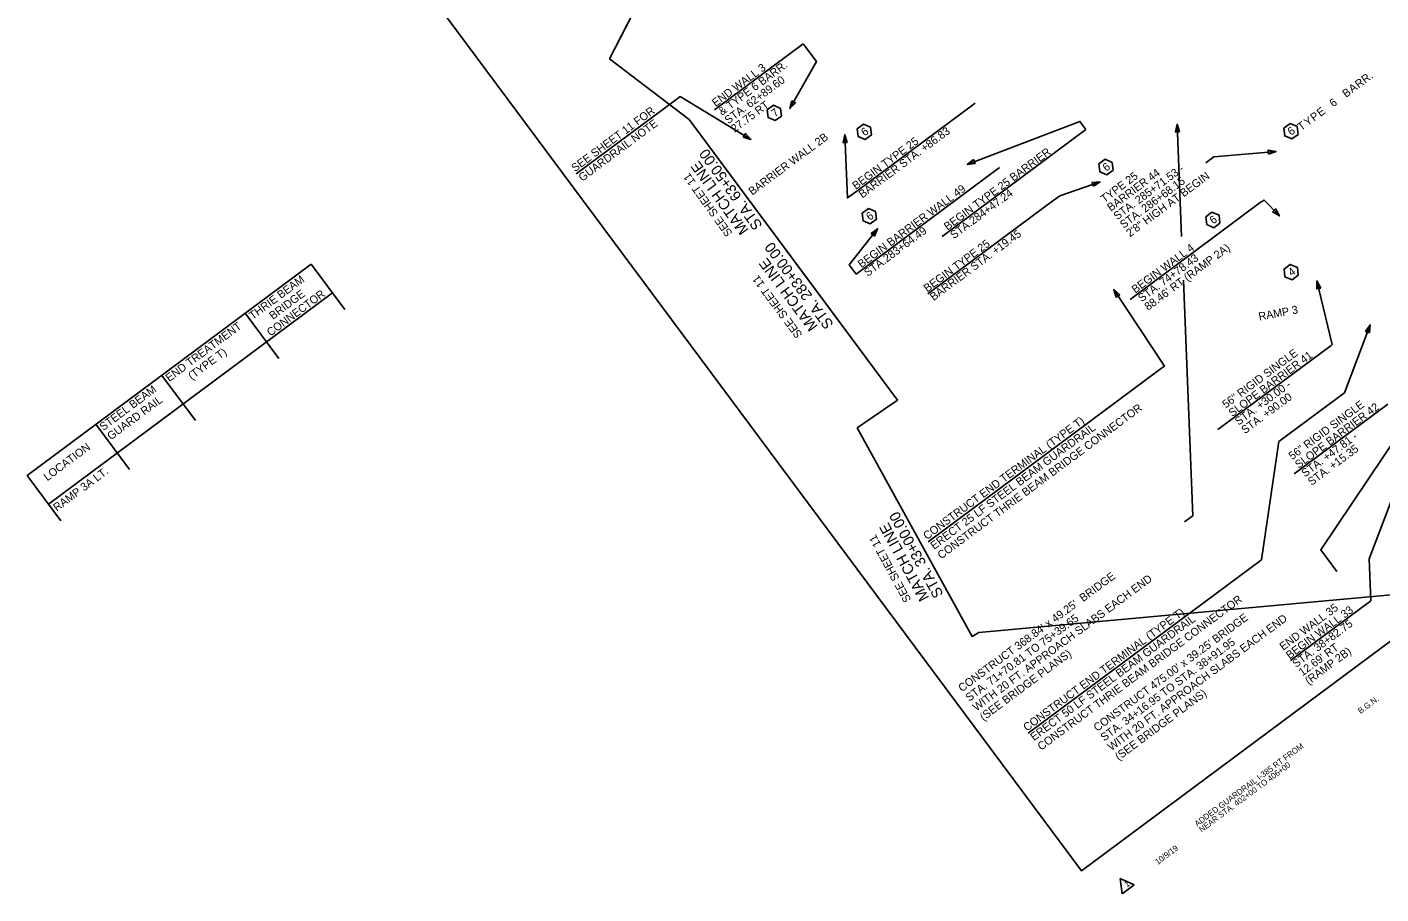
# Model space of a CAD drawing. Extents: x 1609621 to 1611756, y 1093008 to 1094970.
# Drawn here: x 1609621 to 1610636, y 1093008 to 1093658 of the extents above; entities that cross this region are included whole.
import ezdxf

# ---------------------------------------------------------------- set-up
doc = ezdxf.new("R2010")
doc.units = 0
for name, color, linetype in [('Level 2', 7, 'Continuous'), ('Plan_Clip', 7, 'Continuous'), ('RD_PD_GR_TX', 7, 'Continuous'), ('RD_SHT_MatchLine', 7, 'Continuous'), ('RD_SHT_TX', 7, 'Continuous'), ('RD_TX_Bridge', 7, 'Continuous'), ('RD_TX_RoadID', 7, 'Continuous')]:
    doc.layers.add(name, color=color, linetype=linetype)

msp = doc.modelspace()

# ---------------------------------------------------------------- linework, layer by layer
at = {"layer": 'Level 2'}
msp.add_lwpolyline([(1609840.9, 1093793), (1611185.2, 1094792.2), (1611755.8, 1094024.6), (1610411.6, 1093025.3)], close=True, dxfattribs=at)
at = {"layer": 'Plan_Clip'}
msp.add_lwpolyline([(1610675.5, 1094282.2), (1610541, 1094302.1), (1610507.1, 1094195.8), (1610487.7, 1094201.2), (1610383.3, 1094027.8), (1610263.9, 1094064.6), (1610138, 1093954.5), (1610138.1, 1093790.9), (1610057.7, 1093634.1), (1610117.5, 1093588.6), (1610273.7, 1093378.3), (1610243.5, 1093357.4), (1610329.6, 1093201), (1610334.7, 1093203.9), (1610646.7, 1093232.4)], dxfattribs=at)
msp.add_lwpolyline([(1610675.5, 1094282.2), (1610541, 1094302.1), (1610507.1, 1094195.8), (1610487.7, 1094201.2), (1610383.3, 1094027.8), (1610263.9, 1094064.6), (1610138, 1093954.5), (1610138.1, 1093790.9), (1610057.7, 1093634.1), (1610117.5, 1093588.6), (1610273.7, 1093378.3), (1610243.5, 1093357.4), (1610329.6, 1093201), (1610334.7, 1093203.9), (1610646.7, 1093232.4)], dxfattribs=at)
at = {"layer": 'RD_PD_GR_TX'}
for p, q in [((1610107.4, 1093603.5), (1610032.7, 1093547.9)), ((1609620.9, 1093321.8), (1609833.9, 1093480.1)), ((1609833.9, 1093480.1), (1609859.1, 1093446.2)), ((1609636.8, 1093300.3), (1609849.8, 1093458.7)), ((1609784.5, 1093443.4), (1609809.7, 1093409.5)), ((1609721.8, 1093396.8), (1609747.1, 1093362.9)), ((1610471.6, 1093402.1), (1610296.6, 1093272)), ((1609672.4, 1093360.1), (1609697.6, 1093326.2)), ((1609620.9, 1093321.8), (1609646.1, 1093287.8)), ((1610546.6, 1093258.5), (1610371.5, 1093128.4))]:
    msp.add_line(p, q, dxfattribs=at)
for points in [[(1610107.4, 1093603.5), (1610110.7, 1093605.9), (1610163.7, 1093573.7)], [(1610471.6, 1093402.1), (1610473.8, 1093403.7), (1610435.8, 1093461.1)], [(1610546.6, 1093258.5), (1610559.6, 1093347.1), (1610608.9, 1093383.7), (1610628.2, 1093434.6)]]:
    msp.add_lwpolyline(points, dxfattribs=at)
for points in [[(1610158, 1093575.4), (1610163.7, 1093573.7), (1610159.6, 1093578.1)], [(1610440.3, 1093457.2), (1610435.8, 1093461.1), (1610437.7, 1093455.4)], [(1610627.6, 1093428.6), (1610628.2, 1093434.6), (1610624.7, 1093429.7)]]:
    msp.add_lwpolyline(points, close=True, dxfattribs=at)
at = {"layer": 'RD_SHT_MatchLine'}
for p, q in [((1610138.1, 1093790.9), (1610057.7, 1093634.1)), ((1610243.5, 1093357.4), (1610329.6, 1093201))]:
    msp.add_line(p, q, dxfattribs=at)
msp.add_lwpolyline([(1610273.7, 1093378.3), (1610206.9, 1093468.2), (1610117.5, 1093588.6)], dxfattribs=at)
at = {"layer": 'RD_SHT_TX'}
for p, q in [((1610202.9, 1093645.5), (1610136.4, 1093596)), ((1610331.9, 1093601), (1610243.1, 1093535)), ((1610414.9, 1093581.1), (1610307.2, 1093501)), ((1610350.1, 1093552.7), (1610242.6, 1093472.8)), ((1610385.4, 1093524.1), (1610296.5, 1093458)), ((1610545.6, 1093526.3), (1610448, 1093453.8)), ((1610598.9, 1093419.3), (1610513.9, 1093356.2)), ((1610641.3, 1093375.1), (1610571.1, 1093322.9)), ((1610628.5, 1093227.7), (1610568.3, 1093182.9)), ((1610440.6, 1093019.4), (1610451.2, 1093014.7)), ((1610440.6, 1093019.4), (1610442.1, 1093007.9)), ((1610442.1, 1093007.9), (1610451.2, 1093014.7))]:
    msp.add_line(p, q, dxfattribs=at)
for points in [[(1610202.9, 1093645.5), (1610212.8, 1093632.2), (1610193, 1093596.8)], [(1610414.9, 1093581.1), (1610410.4, 1093587.2), (1610325.9, 1093555)], [(1610243.1, 1093535), (1610236.1, 1093529.8), (1610234.1, 1093577.2)], [(1610504.9, 1093556.2), (1610510.8, 1093560.6), (1610557.6, 1093564.7)], [(1610385.4, 1093524.1), (1610395.4, 1093531.5), (1610425.6, 1093541.9)], [(1610545.6, 1093526.3), (1610548.6, 1093528.2), (1610560.1, 1093516.4)], [(1610242.6, 1093472.8), (1610237.4, 1093479.8), (1610258.7, 1093506.7)], [(1610598.9, 1093419.3), (1610599.6, 1093419.9), (1610588.2, 1093467.6)], [(1610628.5, 1093227.7), (1610627.3, 1093259.3), (1610675.6, 1093385.8)]]:
    msp.add_lwpolyline(points, dxfattribs=at)
for points in [[(1610186, 1093597), (1610180.7, 1093599.3), (1610176, 1093595.9), (1610176.7, 1093590.1), (1610182, 1093587.8), (1610186.7, 1093591.2)], [(1610194.5, 1093602.6), (1610193, 1093596.8), (1610197.2, 1093601.1)], [(1610253.4, 1093582.9), (1610248.1, 1093585.2), (1610243.4, 1093581.7), (1610244.1, 1093576), (1610249.4, 1093573.6), (1610254.1, 1093577.1)], [(1610573.3, 1093583.3), (1610568, 1093585.6), (1610563.3, 1093582.1), (1610564, 1093576.4), (1610569.3, 1093574.1), (1610574, 1093577.5)], [(1610235.9, 1093571.5), (1610234.1, 1093577.2), (1610232.8, 1093571.3)], [(1610330.7, 1093558.6), (1610325.9, 1093555), (1610331.8, 1093555.6)], [(1610434.6, 1093556.4), (1610429.3, 1093558.8), (1610424.6, 1093555.3), (1610425.3, 1093549.5), (1610430.6, 1093547.2), (1610435.3, 1093550.7)], [(1610551.9, 1093562.6), (1610557.6, 1093564.7), (1610551.7, 1093565.7)], [(1610420.6, 1093538.6), (1610425.6, 1093541.9), (1610419.6, 1093541.5)], [(1610257.2, 1093519.6), (1610251.8, 1093521.9), (1610247.2, 1093518.5), (1610247.8, 1093512.7), (1610253.2, 1093510.4), (1610257.8, 1093513.9)], [(1610514.8, 1093516.8), (1610509.4, 1093519.1), (1610504.8, 1093515.6), (1610505.5, 1093509.8), (1610510.8, 1093507.5), (1610515.4, 1093511)], [(1610554.9, 1093519.5), (1610560.1, 1093516.4), (1610557.2, 1093521.6)], [(1610256.3, 1093501.2), (1610258.7, 1093506.7), (1610253.9, 1093503.1)], [(1610573.5, 1093477.7), (1610568.2, 1093480), (1610563.5, 1093476.5), (1610564.2, 1093470.8), (1610569.5, 1093468.5), (1610574.2, 1093471.9)], [(1610591.1, 1093462.3), (1610588.2, 1093467.6), (1610588.1, 1093461.6)]]:
    msp.add_lwpolyline(points, close=True, dxfattribs=at)
at = {"layer": 'RD_TX_Bridge'}
msp.add_lwpolyline([(1610485.1, 1093579.4), (1610483.3, 1093585.1), (1610482, 1093579.3)], close=True, dxfattribs=at)
for points in [[(1610486.7, 1093500.8), (1610483.3, 1093585.1)], [(1610488.9, 1093286.9), (1610495.1, 1093291.5), (1610488, 1093468.3)], [(1610603, 1093249.8), (1610591.1, 1093266), (1610673.9, 1093389.1)]]:
    msp.add_lwpolyline(points, dxfattribs=at)

# ---------------------------------------------------------------- texts
at = {"layer": 'RD_PD_GR_TX'}
for s, rotation, p in [('SEE SHEET 11 FOR', 36.6272, (1610031.8, 1093549.1)), ('GUARDRAIL NOTE', 36.6272, (1610037.2, 1093541.9)), ('THRIE BEAM', 36.6256, (1609790.1, 1093438.3)), ('CONNECTOR', 36.6256, (1609803.4, 1093425.8)), ('BRIDGE', 36.6256, (1609805.2, 1093438.3)), ('END TREATMENT', 36.6256, (1609727.5, 1093391.7)), ('(TYPE T)', 36.6256, (1609744.4, 1093393.1)), ('STEEL BEAM', 36.6256, (1609678, 1093355)), ('GUARD RAIL', 36.6256, (1609683.7, 1093348)), ('CONSTRUCT THRIE BEAM BRIDGE CONNECTOR', 36.6272, (1610306.4, 1093258.7)), ('CONSTRUCT END TERMINAL (TYPE T)', 36.6272, (1610295.7, 1093273.2)), ('ERECT 25 LF STEEL BEAM GUARDRAIL', 36.6272, (1610301.1, 1093265.9)), ('LOCATION', 36.6256, (1609636, 1093317.3)), ('RAMP 3A LT.', 36.6256, (1609643.2, 1093294.5)), ('CONSTRUCT THRIE BEAM BRIDGE CONNECTOR', 36.6272, (1610381.4, 1093115.2)), ('CONSTRUCT END TERMINAL (TYPE T)', 36.6272, (1610370.7, 1093129.6)), ('ERECT 50 LF STEEL BEAM GUARDRAIL', 36.6272, (1610376, 1093122.4))]:
    msp.add_text(s, height=6, rotation=rotation, dxfattribs=at).set_placement(p)
at = {"layer": 'RD_SHT_MatchLine'}
for s, height, rotation, p in [('MATCH LINE', 8, 125.7795, (1610162.4, 1093505.8)), ('STA. 63+50.00', 8, 125.7795, (1610172.7, 1093509.4)), ('SEE SHEET 11', 6, 125.7561, (1610150.2, 1093503.5)), ('STA. 283+00.00', 8, 126.6256, (1610226.1, 1093435.2)), ('MATCH LINE', 8, 126.6256, (1610214.2, 1093433.6)), ('SEE SHEET 11', 6, 126.6769, (1610202.6, 1093427.4)), ('STA. 33+00.00', 8, 118.5477, (1610308.3, 1093232.5)), ('MATCH LINE', 8, 118.5477, (1610297.6, 1093230.1)), ('SEE SHEET 11', 6, 118.599, (1610284.1, 1093228.5))]:
    msp.add_text(s, height=height, rotation=rotation, dxfattribs=at).set_placement(p)
at = {"layer": 'RD_SHT_TX'}
for s, height, p in [('END WALL 3', 6, (1610137.2, 1093597.9)), ('& TYPE 6 BARR.', 6, (1610142, 1093591.4)), ('STA. 62+89.60', 6, (1610146.7, 1093585)), ('R', 6, (1610619.5, 1093611.9)), ('R', 6, (1610624.3, 1093615.5)), ('.', 6, (1610629.1, 1093619)), ('B', 6, (1610610, 1093604.8)), ('A', 6, (1610614.7, 1093608.4)), ('27.75 RT', 6, (1610151.5, 1093578.6)), ('E', 6, (1610590.8, 1093590.5)), ('6', 6, (1610600.4, 1093597.7)), ('7', 6, (1610181.7, 1093590.1)), ('Y', 6, (1610581.2, 1093583.4)), ('P', 6, (1610586, 1093587)), ('BARRIER WALL 2B', 6, (1610164.7, 1093531.5)), ('BARRIER STA. +86.83', 6, (1610247.3, 1093529.4)), ('6', 6, (1610249, 1093575.9)), ('6', 6, (1610568.9, 1093576.3)), ('T', 6, (1610576.4, 1093579.9)), ('BEGIN TYPE 25 ', 6, (1610242.5, 1093535.8)), ('BEGIN TYPE 25 BARRIER', 6, (1610311.2, 1093505.2)), ('TYPE 25', 6, (1610428.8, 1093525.9)), ('6', 6, (1610430.2, 1093549.4)), ('BARRIER 44', 6, (1610433.6, 1093519.5)), ('STA. 285+71.53 -', 6, (1610438.4, 1093513)), ('2\'8" HIGH AT BEGIN', 6, (1610447.9, 1093500.2)), ('BEGIN BARRIER WALL 49', 6, (1610246.6, 1093477)), ('STA. 286+68.15', 6, (1610443.2, 1093506.6)), ('STA.284+47.24', 6, (1610315.9, 1093498.8)), ('6', 6, (1610252.8, 1093512.6)), ('6', 6, (1610510.4, 1093509.8)), ('STA.283+64.49', 6, (1610251.3, 1093470.6)), ('BEGIN TYPE 25 ', 6, (1610296, 1093458.9)), ('BARRIER STA. +19.45', 6, (1610300.7, 1093452.4)), ('BEGIN WALL 4', 6, (1610452, 1093458)), ('STA. 74+78.43', 6, (1610456.8, 1093451.5)), ("88.46' RT (RAMP 2A)", 6, (1610461.6, 1093445.1)), ('4', 6, (1610569.2, 1093470.8)), ('56" RIGID SINGLE', 6, (1610519.9, 1093371.8)), ('SLOPE BARRIER 41', 6, (1610524.7, 1093365.4)), ('STA. +30.00 -', 6, (1610529.4, 1093359)), ('STA. +90.00', 6, (1610534.2, 1093352.6)), ('56" RIGID SINGLE', 6, (1610569.7, 1093333.1)), ('SLOPE BARRIER 42', 6, (1610574.5, 1093326.6)), ('STA. +47.81 -', 6, (1610579.3, 1093320.2)), ('STA. +15.35', 6, (1610584.1, 1093313.8)), ('END WALL 35', 6, (1610562.9, 1093190.2)), ('BEGIN WALL 33', 6, (1610567.7, 1093183.7)), ('STA. 38+82.75', 6, (1610572.5, 1093177.3)), ("12.69' RT ", 6, (1610577.3, 1093170.9)), ('(RAMP 2B)', 6, (1610582, 1093164.5)), ('B.G.N.', 4.4, (1610620.9, 1093142.7)), ('ADDED GUARDRAIL I-385 RT FROM', 4.4, (1610498.4, 1093058.2)), ('NEAR STA. 402+00 TO 406+00', 4.4, (1610501.7, 1093053.8)), ('10/9/19', 4.4, (1610468.8, 1093029.6)), ('1', 4.4, (1610445.7, 1093012.6))]:
    msp.add_text(s, height=height, rotation=36.6256, dxfattribs=at).set_placement(p)
at = {"layer": 'RD_TX_Bridge'}
for s, p in [("CONSTRUCT 368.84' x 49.25'  BRIDGE", (1610322, 1093159.1)), ('WITH 20 FT. APPROACH SLABS EACH END', (1610332.8, 1093144.7)), ('STA. 71+70.81 TO 75+39.65', (1610327.4, 1093151.9)), ("CONSTRUCT 475.00' x 39.25' BRIDGE", (1610423.4, 1093129.4)), ('WITH 20 FT. APPROACH SLABS EACH END', (1610434.1, 1093114.9)), ('STA. 34+16.95 TO STA. 38+91.95', (1610428.7, 1093122.1)), ('(SEE BRIDGE PLANS)', (1610338.1, 1093137.4)), ('(SEE BRIDGE PLANS)', (1610439.5, 1093107.7))]:
    msp.add_text(s, height=6, rotation=36.6256, dxfattribs=at).set_placement(p)
at = {"layer": 'RD_TX_RoadID'}
msp.add_text('RAMP 3', height=6, rotation=10.5339, dxfattribs=at).set_placement((1610545, 1093437.9))

doc.saveas('drawing.dxf')
